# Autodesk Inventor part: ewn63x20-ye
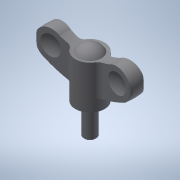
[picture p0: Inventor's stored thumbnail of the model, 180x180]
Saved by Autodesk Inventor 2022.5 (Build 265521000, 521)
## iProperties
Created: 2017-05
Part Number: ewn63x20-ye
Material: 一般
Document SubType Name: Modeling
Designer: imaocorp
Density: 1 g/cm^3
Appearance: 既定
Author: imaocorp
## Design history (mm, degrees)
node "ewn63x20-ye.x_t1"
node "ewn63x20-ye"
node "Base1"
